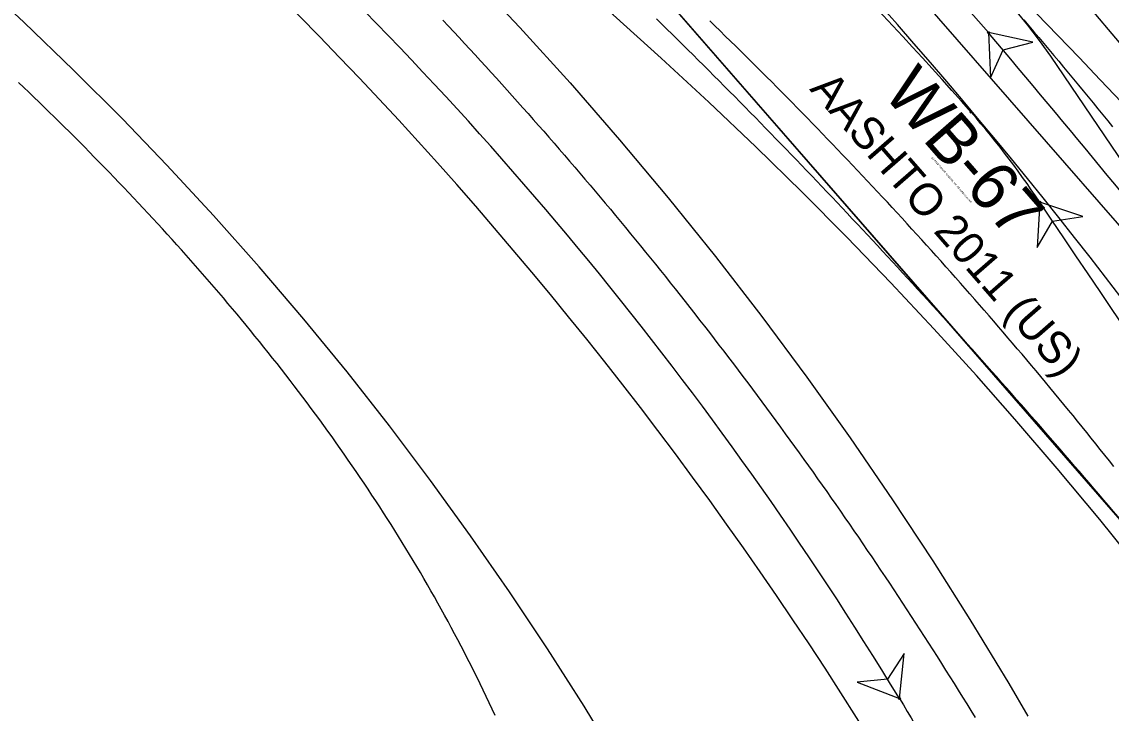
# Model space of a CAD drawing. Extents: x 2175591 to 2194071, y 76570 to 86955.
# Drawn here: x 2192868.19 to 2192916.27, y 86856.73 to 86887.24 of the extents above; entities that cross this region are included whole.
import ezdxf

# ---------------------------------------------------------------- set-up
doc = ezdxf.new("R2010")
doc.units = 0
doc.layers.add('-NOPLT', color=7, linetype='Continuous')
doc.layers.add('C-UTIL-STRM-TEXT', color=7, linetype='Continuous')

msp = doc.modelspace()

# ---------------------------------------------------------------- linework, layer by layer
at = {"layer": '-NOPLT'}
for points in [[(2192886.779, 86887.308), (2192887.017, 86887.054), (2192887.255, 86886.8), (2192887.492, 86886.545), (2192887.729, 86886.29), (2192887.965, 86886.034), (2192888.201, 86885.778), (2192888.436, 86885.521), (2192888.671, 86885.264), (2192888.905, 86885.007), (2192889.139, 86884.749), (2192889.373, 86884.491), (2192889.606, 86884.232), (2192889.838, 86883.973), (2192890.07, 86883.713), (2192890.302, 86883.453), (2192890.533, 86883.193), (2192890.763, 86882.932), (2192890.994, 86882.67), (2192891.223, 86882.409), (2192891.452, 86882.146), (2192891.681, 86881.884), (2192891.909, 86881.621), (2192892.137, 86881.357), (2192892.365, 86881.093), (2192892.591, 86880.829), (2192892.818, 86880.564), (2192893.044, 86880.299), (2192893.269, 86880.033), (2192893.494, 86879.767), (2192893.718, 86879.501), (2192893.942, 86879.234), (2192894.166, 86878.967), (2192894.389, 86878.699), (2192894.611, 86878.431), (2192894.833, 86878.162), (2192895.055, 86877.893), (2192895.276, 86877.624), (2192895.496, 86877.354), (2192895.716, 86877.084), (2192895.936, 86876.813), (2192896.155, 86876.542), (2192896.374, 86876.27), (2192896.592, 86875.998), (2192896.81, 86875.726), (2192897.027, 86875.453), (2192897.243, 86875.18), (2192897.46, 86874.907), (2192897.675, 86874.633), (2192897.89, 86874.358), (2192898.105, 86874.083), (2192898.319, 86873.808), (2192898.533, 86873.533), (2192898.746, 86873.256), (2192898.959, 86872.98), (2192899.171, 86872.703), (2192899.383, 86872.426), (2192899.594, 86872.148), (2192899.805, 86871.87), (2192900.015, 86871.592), (2192900.225, 86871.313), (2192900.435, 86871.033), (2192900.643, 86870.754), (2192900.852, 86870.473), (2192901.059, 86870.193), (2192901.267, 86869.912), (2192901.474, 86869.631), (2192901.68, 86869.349), (2192901.886, 86869.067), (2192902.091, 86868.784), (2192902.296, 86868.501), (2192902.5, 86868.218), (2192902.704, 86867.934), (2192902.907, 86867.65), (2192903.11, 86867.365), (2192903.312, 86867.08), (2192903.514, 86866.794), (2192903.715, 86866.509), (2192903.916, 86866.222), (2192904.116, 86865.936), (2192904.316, 86865.649), (2192904.516, 86865.361), (2192904.714, 86865.073), (2192904.913, 86864.785), (2192905.11, 86864.496), (2192905.308, 86864.207), (2192905.505, 86863.918), (2192905.701, 86863.628), (2192905.897, 86863.337), (2192906.092, 86863.047), (2192906.287, 86862.755), (2192906.481, 86862.464), (2192906.675, 86862.172), (2192906.868, 86861.879), (2192907.061, 86861.587), (2192907.253, 86861.293), (2192907.445, 86861), (2192907.636, 86860.706), (2192907.827, 86860.411), (2192908.017, 86860.116), (2192908.207, 86859.821), (2192908.396, 86859.525), (2192908.585, 86859.229), (2192908.773, 86858.932), (2192908.961, 86858.635), (2192909.148, 86858.338), (2192909.335, 86858.04), (2192909.521, 86857.742), (2192909.707, 86857.443), (2192909.892, 86857.144), (2192910.077, 86856.845), (2192910.261, 86856.545)], [(2192916.355, 86865.653), (2192916.143, 86865.902), (2192915.931, 86866.151), (2192915.719, 86866.4), (2192915.506, 86866.648), (2192915.294, 86866.897), (2192915.081, 86867.145), (2192914.868, 86867.393), (2192914.655, 86867.64), (2192914.441, 86867.888), (2192914.228, 86868.135), (2192914.014, 86868.382), (2192913.8, 86868.629), (2192913.586, 86868.876), (2192913.371, 86869.122), (2192913.157, 86869.368), (2192912.942, 86869.614), (2192912.727, 86869.86), (2192912.512, 86870.106), (2192912.296, 86870.351), (2192912.081, 86870.596), (2192911.865, 86870.841), (2192911.649, 86871.086), (2192911.433, 86871.33), (2192911.216, 86871.574), (2192910.999, 86871.818), (2192910.782, 86872.062), (2192910.565, 86872.305), (2192910.348, 86872.549), (2192910.13, 86872.792), (2192909.913, 86873.035), (2192909.695, 86873.277), (2192909.476, 86873.519), (2192909.258, 86873.762), (2192909.039, 86874.003), (2192908.821, 86874.245), (2192908.601, 86874.487), (2192908.382, 86874.728), (2192908.163, 86874.969), (2192907.943, 86875.209), (2192907.723, 86875.45), (2192907.503, 86875.69), (2192907.282, 86875.93), (2192907.062, 86876.17), (2192906.841, 86876.409), (2192906.62, 86876.648), (2192906.398, 86876.888), (2192906.177, 86877.126), (2192905.955, 86877.365), (2192905.733, 86877.603), (2192905.511, 86877.841), (2192905.288, 86878.079), (2192905.066, 86878.316), (2192904.843, 86878.554), (2192904.62, 86878.791), (2192904.396, 86879.027), (2192904.173, 86879.264), (2192903.949, 86879.5), (2192903.725, 86879.736), (2192903.5, 86879.972), (2192903.276, 86880.208), (2192903.051, 86880.443), (2192902.826, 86880.678), (2192902.601, 86880.912), (2192902.375, 86881.147), (2192902.15, 86881.381), (2192901.924, 86881.615), (2192901.698, 86881.849), (2192901.471, 86882.082), (2192901.244, 86882.316), (2192901.017, 86882.548), (2192900.79, 86882.781), (2192900.563, 86883.014), (2192900.335, 86883.246), (2192900.107, 86883.478), (2192899.879, 86883.709), (2192899.651, 86883.94), (2192899.422, 86884.172), (2192899.193, 86884.402), (2192898.964, 86884.633), (2192898.735, 86884.863), (2192898.505, 86885.093), (2192898.276, 86885.323), (2192898.046, 86885.552), (2192897.815, 86885.782), (2192897.585, 86886.011), (2192897.354, 86886.239), (2192897.123, 86886.468), (2192896.892, 86886.696), (2192896.66, 86886.923), (2192896.428, 86887.151), (2192896.196, 86887.378)], [(2192916.385, 86867.621), (2192916.187, 86867.871), (2192915.987, 86868.122), (2192915.788, 86868.371), (2192915.588, 86868.621), (2192915.387, 86868.87), (2192915.187, 86869.119), (2192914.985, 86869.368), (2192914.784, 86869.616), (2192914.582, 86869.864), (2192914.379, 86870.111), (2192914.176, 86870.359), (2192913.973, 86870.606), (2192913.769, 86870.852), (2192913.565, 86871.098), (2192913.361, 86871.344), (2192913.156, 86871.59), (2192912.95, 86871.835), (2192912.745, 86872.08), (2192912.539, 86872.325), (2192912.332, 86872.569), (2192912.125, 86872.813), (2192911.918, 86873.057), (2192911.71, 86873.3), (2192911.502, 86873.543), (2192911.293, 86873.786), (2192911.084, 86874.029), (2192910.875, 86874.271), (2192910.665, 86874.512), (2192910.455, 86874.754), (2192910.245, 86874.995), (2192910.034, 86875.235), (2192909.823, 86875.476), (2192909.611, 86875.716), (2192909.399, 86875.956), (2192909.186, 86876.195), (2192908.974, 86876.434), (2192908.76, 86876.673), (2192908.547, 86876.911), (2192908.333, 86877.149), (2192908.118, 86877.387), (2192907.904, 86877.624), (2192907.689, 86877.861), (2192907.473, 86878.098), (2192907.257, 86878.334), (2192907.041, 86878.57), (2192906.824, 86878.806), (2192906.607, 86879.041), (2192906.39, 86879.276), (2192906.172, 86879.511), (2192905.954, 86879.745), (2192905.735, 86879.979), (2192905.516, 86880.213), (2192905.297, 86880.446), (2192905.077, 86880.679), (2192904.857, 86880.912), (2192904.637, 86881.144), (2192904.416, 86881.376), (2192904.195, 86881.608), (2192903.973, 86881.839), (2192903.751, 86882.07), (2192903.529, 86882.3), (2192903.306, 86882.53), (2192903.083, 86882.76), (2192902.86, 86882.99), (2192902.636, 86883.219), (2192902.412, 86883.448), (2192902.188, 86883.676), (2192901.963, 86883.904), (2192901.738, 86884.132), (2192901.512, 86884.36), (2192901.286, 86884.587), (2192901.06, 86884.814), (2192900.833, 86885.04), (2192900.606, 86885.266), (2192900.379, 86885.492), (2192900.151, 86885.717), (2192899.923, 86885.942), (2192899.695, 86886.167), (2192899.466, 86886.391), (2192899.237, 86886.615), (2192899.008, 86886.838), (2192898.778, 86887.062), (2192898.548, 86887.285)], [(2192912.414, 86887.322), (2192912.634, 86887.063), (2192912.855, 86886.803), (2192913.075, 86886.543), (2192913.294, 86886.283), (2192913.513, 86886.022), (2192913.732, 86885.762), (2192913.95, 86885.5), (2192914.168, 86885.239), (2192914.386, 86884.977), (2192914.603, 86884.715), (2192914.82, 86884.452), (2192915.036, 86884.19), (2192915.252, 86883.927), (2192915.468, 86883.663), (2192915.683, 86883.4), (2192915.898, 86883.136), (2192916.113, 86882.871), (2192916.327, 86882.607)], [(2192889.079, 86856.635), (2192888.949, 86856.915), (2192888.818, 86857.195), (2192888.686, 86857.475), (2192888.552, 86857.753), (2192888.417, 86858.032), (2192888.281, 86858.309), (2192888.144, 86858.586), (2192888.005, 86858.863), (2192887.865, 86859.138), (2192887.724, 86859.414), (2192887.582, 86859.688), (2192887.438, 86859.963), (2192887.293, 86860.236), (2192887.147, 86860.509), (2192887, 86860.781), (2192886.852, 86861.053), (2192886.702, 86861.324), (2192886.551, 86861.595), (2192886.399, 86861.865), (2192886.246, 86862.134), (2192886.092, 86862.403), (2192885.937, 86862.671), (2192885.78, 86862.938), (2192885.622, 86863.205), (2192885.464, 86863.471), (2192885.304, 86863.737), (2192885.143, 86864.002), (2192884.981, 86864.267), (2192884.817, 86864.531), (2192884.653, 86864.794), (2192884.488, 86865.056), (2192884.321, 86865.318), (2192884.154, 86865.58), (2192883.985, 86865.841), (2192883.816, 86866.101), (2192883.645, 86866.36), (2192883.473, 86866.619), (2192883.301, 86866.877), (2192883.127, 86867.135), (2192882.952, 86867.392), (2192882.777, 86867.649), (2192882.6, 86867.904), (2192882.422, 86868.16), (2192882.244, 86868.414), (2192882.064, 86868.668), (2192881.884, 86868.922), (2192881.702, 86869.174), (2192881.52, 86869.426), (2192881.337, 86869.678), (2192881.153, 86869.929), (2192880.967, 86870.179), (2192880.781, 86870.429), (2192880.595, 86870.678), (2192880.407, 86870.926), (2192880.218, 86871.174), (2192880.029, 86871.421), (2192879.838, 86871.668), (2192879.647, 86871.914), (2192879.455, 86872.159), (2192879.262, 86872.404), (2192879.068, 86872.648), (2192878.874, 86872.891), (2192878.678, 86873.134), (2192878.482, 86873.377), (2192878.285, 86873.618), (2192878.087, 86873.859), (2192877.889, 86874.1), (2192877.689, 86874.34), (2192877.489, 86874.579), (2192877.288, 86874.818), (2192877.087, 86875.056), (2192876.884, 86875.294), (2192876.681, 86875.531), (2192876.478, 86875.767), (2192876.273, 86876.003), (2192876.068, 86876.238), (2192875.862, 86876.473), (2192875.655, 86876.707), (2192875.448, 86876.94), (2192875.24, 86877.173), (2192875.032, 86877.406), (2192874.822, 86877.638), (2192874.612, 86877.869), (2192874.402, 86878.1), (2192874.191, 86878.33), (2192873.979, 86878.559), (2192873.766, 86878.788), (2192873.553, 86879.017), (2192873.34, 86879.245), (2192873.126, 86879.472), (2192872.911, 86879.699), (2192872.695, 86879.926), (2192872.479, 86880.152), (2192872.263, 86880.377), (2192872.046, 86880.602), (2192871.828, 86880.826), (2192871.61, 86881.05), (2192871.391, 86881.273), (2192871.172, 86881.496), (2192870.952, 86881.718), (2192870.732, 86881.94), (2192870.511, 86882.161), (2192870.29, 86882.382), (2192870.068, 86882.603), (2192869.846, 86882.822), (2192869.623, 86883.042), (2192869.4, 86883.261), (2192869.176, 86883.479), (2192868.952, 86883.697), (2192868.728, 86883.915), (2192868.503, 86884.132), (2192868.277, 86884.349), (2192868.051, 86884.565)]]:
    msp.add_lwpolyline(points, dxfattribs=at)
for centre, radius, start, end in [((2192733.134, 86734.566), 231.18, 31.07167, 66.3451), ((2192748.446, 86757.375), 185.351, 28.75355, 79.22293), ((2192746.129, 86724.49), 233.336, 23.25976, 66.11585)]:
    msp.add_arc(centre, radius, start, end, dxfattribs=at)
at = {"layer": 'C-UTIL-STRM-TEXT'}
for p, q in [((2192930.117, 86862.772), (2192895.297, 86902.728)), ((2192888.889, 86897.143), (2192923.709, 86857.187))]:
    msp.add_line(p, q, dxfattribs=at)
for points in [[(2192917.573, 86863.028), (2192915.761, 86865.28), (2192913.888, 86867.533), (2192912.022, 86869.708), (2192910.323, 86871.631), (2192908.446, 86873.695), (2192906.547, 86875.724), (2192904.608, 86877.736), (2192902.637, 86879.722), (2192900.592, 86881.724), (2192898.512, 86883.702), (2192896.411, 86885.642), (2192894.283, 86887.552), (2192892.129, 86889.43), (2192855.115, 86920.736)], [(2192877.902, 86918.123), (2192880.493, 86916.45), (2192883.074, 86914.757), (2192885.663, 86913.122), (2192888.231, 86911.437), (2192890.762, 86909.709), (2192893.265, 86907.934), (2192895.503, 86906.286), (2192897.957, 86904.413), (2192900.389, 86902.485), (2192902.803, 86900.496), (2192905.181, 86898.462), (2192907.521, 86896.384), (2192908.676, 86895.329), (2192909.799, 86894.239), (2192910.865, 86893.103), (2192912.907, 86890.727), (2192916.943, 86885.948)], [(2192918.377, 86863.304), (2192888.843, 86897.193), (2192886.338, 86899.259), (2192885.072, 86900.273), (2192873.793, 86910.218), (2192879.084, 86916.218), (2192881.632, 86914.496), (2192884.364, 86912.575), (2192887.079, 86910.585), (2192889.766, 86908.535), (2192892.42, 86906.426), (2192895.034, 86904.264), (2192897.605, 86902.051), (2192900.132, 86899.788), (2192902.613, 86897.477), (2192905.048, 86895.117), (2192907.435, 86892.712), (2192909.773, 86890.261), (2192911.489, 86888.389), (2192912.039, 86887.745), (2192912.573, 86887.088), (2192913.091, 86886.416), (2192913.594, 86885.73), (2192920.735, 86875.173)], [(2192866.026, 86908.2), (2192868.679, 86906.211), (2192871.293, 86904.193), (2192873.903, 86902.116), (2192876.41, 86900.063), (2192878.973, 86897.9), (2192881.501, 86895.704), (2192882.133, 86895.138), (2192883.35, 86893.979), (2192885.561, 86891.8), (2192887.891, 86889.417), (2192890.175, 86886.989), (2192892.388, 86884.543), (2192894.575, 86882.031), (2192896.715, 86879.476), (2192898.805, 86876.88), (2192900.846, 86874.242), (2192902.837, 86871.564), (2192904.753, 86868.88), (2192906.622, 86866.154), (2192908.394, 86863.461), (2192910.036, 86860.863), (2192911.75, 86858.04), (2192912.594, 86856.603)], [(2192910.847, 86886.763), (2192910.632, 86887.017), (2192910.415, 86887.27), (2192910.195, 86887.521), (2192909.974, 86887.77), (2192909.75, 86888.017), (2192909.524, 86888.262), (2192909.296, 86888.505), (2192909.066, 86888.746), (2192908.834, 86888.986), (2192908.599, 86889.223), (2192908.363, 86889.457), (2192908.124, 86889.69)], [(2192894.581, 86854.444), (2192893.005, 86857.038), (2192891.384, 86859.579), (2192889.711, 86862.09), (2192887.995, 86864.563), (2192886.232, 86867.005), (2192884.418, 86869.414), (2192882.553, 86871.789), (2192880.637, 86874.127), (2192878.669, 86876.431), (2192876.653, 86878.698), (2192874.591, 86880.923), (2192872.629, 86882.961), (2192870.48, 86885.11), (2192868.285, 86887.223), (2192866.05, 86889.294)], [(2192913.118, 86879.28), (2192912.931, 86879.557), (2192912.742, 86879.831), (2192912.552, 86880.105), (2192912.359, 86880.377), (2192912.163, 86880.647), (2192911.966, 86880.915), (2192911.767, 86881.182), (2192911.565, 86881.448), (2192911.361, 86881.711), (2192911.154, 86881.973), (2192910.946, 86882.233), (2192910.735, 86882.491), (2192910.521, 86882.747), (2192910.306, 86883.001), (2192910.088, 86883.254)], [(2192906.922, 86857.385), (2192907.095, 86857.1), (2192907.266, 86856.814), (2192907.434, 86856.526), (2192907.599, 86856.236)]]:
    msp.add_lwpolyline(points, dxfattribs=at)
for points in [[(2192910.847, 86886.763), (2192910.943, 86884.765), (2192911.493, 86886), (2192912.802, 86886.338)], [(2192913.118, 86879.28), (2192912.997, 86877.284), (2192913.677, 86878.452), (2192915.015, 86878.647)], [(2192906.922, 86857.385), (2192907.136, 86859.373), (2192906.402, 86858.239), (2192905.057, 86858.106)]]:
    msp.add_lwpolyline(points, close=True, dxfattribs=at)
for centre in [(2192910.847, 86886.763), (2192910.847, 86886.763), (2192910.088, 86883.254), (2192910.088, 86883.254), (2192913.118, 86879.28), (2192913.118, 86879.28), (2192906.922, 86857.385), (2192906.922, 86857.385)]:
    msp.add_circle(centre, 0.0417, dxfattribs=at)
for centre, radius, start, end in [((2192783.659, 86772.261), 168.236, 41.2801, 55.29768), ((2192763.098, 86769.778), 168.405, 31.34657, 47.47016), ((2192435.878, 86484.768), 622.25, 38.735142, 40.243229), ((2189178.701, 84356.713), 4506.574, 33.265118, 34.0387)]:
    msp.add_arc(centre, radius, start, end, dxfattribs=at)

# ---------------------------------------------------------------- texts
for s, height, p in [('WB-67', 2.125, (2192906.141, 86884.074)), ('AASHTO 2011 (US)', 1.41667, (2192902.926, 86884.259)), ('(c) 2019 Transoft Solutions, Inc. All rights reserved.', 0.085, (2192908.333, 86881.236))]:
    msp.add_text(s, height=height, rotation=311.0712, dxfattribs=at).set_placement(p)

doc.saveas('drawing.dxf')
